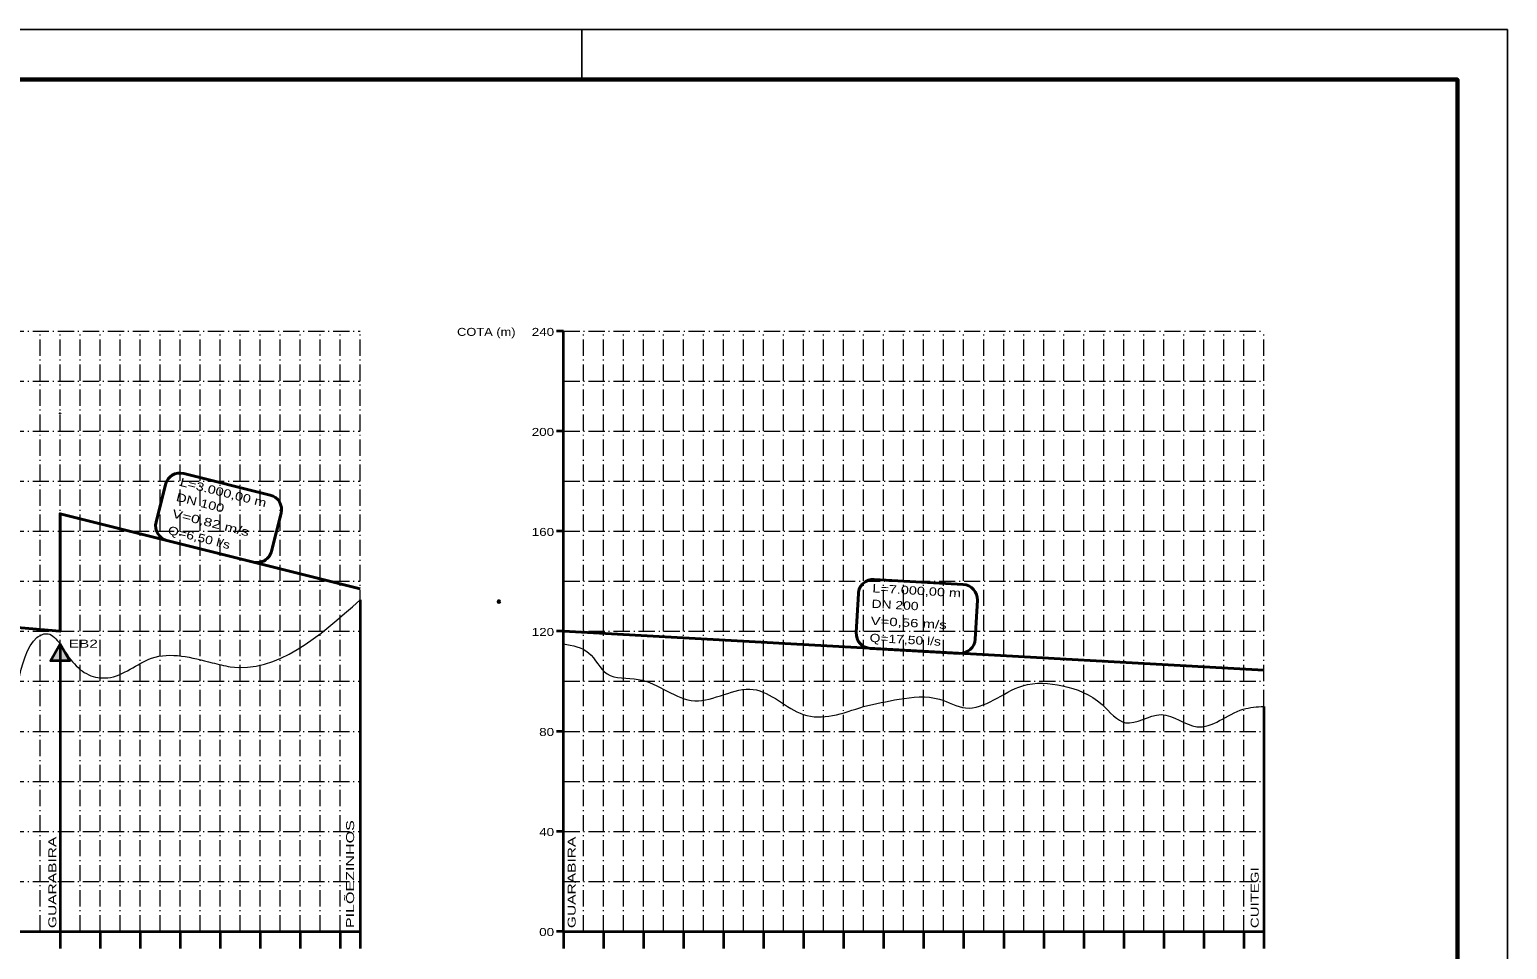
# Model space of a CAD drawing. Extents: x 0 to 1772, y 0 to 1188.
# Drawn here: x 1181 to 1772, y 820 to 1188 of the extents above; entities that cross this region are included whole.
import ezdxf
from ezdxf.enums import TextEntityAlignment as Align

# ---------------------------------------------------------------- set-up
doc = ezdxf.new("R2010")
doc.units = 0
doc.header["$LTSCALE"] = 1.3
doc.header["$PDMODE"] = 32
doc.header["$PDSIZE"] = 0.65
doc.linetypes.add('DOT_DASHED', pattern=[7.7, 5, -1.2, 0.3, -1.2])
for name, color, linetype, lineweight in [('1', 7, 'DOT_DASHED', 13), ('24', 7, 'Continuous', 35), ('55', 7, 'Continuous', 13), ('62', 7, 'Continuous', 13), ('63', 7, 'Continuous', 25), ('9', 7, 'Continuous', 40)]:
    doc.layers.add(name, color=color, linetype=linetype, lineweight=lineweight)

msp = doc.modelspace()

# ---------------------------------------------------------------- hatches: boundary and pattern name
at = {"layer": '62'}
msp.add_hatch(color=256, dxfattribs=at).paths.add_polyline_path([(1193.175, 942.213), (1197.121, 935.475), (1189.312, 935.427)])

# ---------------------------------------------------------------- linework, layer by layer
at = {"layer": '1'}
for p, q in [((121.175, 1067.213), (1313.175, 1067.213)), ((1185.175, 827.213), (1185.175, 1067.213)), ((1193.175, 827.213), (1193.175, 1067.213)), ((1201.175, 827.213), (1201.175, 1067.213)), ((1209.175, 827.213), (1209.175, 1067.213)), ((1217.175, 827.213), (1217.175, 1067.213)), ((1225.175, 827.213), (1225.175, 1067.213)), ((1233.175, 827.213), (1233.175, 1067.213)), ((1241.175, 827.213), (1241.175, 1067.213)), ((1249.175, 827.213), (1249.175, 1067.213)), ((1257.175, 827.213), (1257.175, 1067.213)), ((1265.175, 827.213), (1265.175, 1067.213)), ((1273.175, 827.213), (1273.175, 1067.213)), ((1281.175, 827.213), (1281.175, 1067.213)), ((1289.175, 827.213), (1289.175, 1067.213)), ((1297.175, 827.213), (1297.175, 1067.213)), ((1305.175, 827.213), (1305.175, 1067.213)), ((1313.175, 827.213), (1313.175, 1067.213)), ((1394.428, 1067.213), (1674.428, 1067.213)), ((1402.428, 827.213), (1402.428, 1067.213)), ((1410.428, 827.213), (1410.428, 1067.213)), ((1418.428, 827.213), (1418.428, 1067.213)), ((1426.428, 827.213), (1426.428, 1067.213)), ((1434.428, 827.213), (1434.428, 1067.213)), ((1442.428, 827.213), (1442.428, 1067.213)), ((1450.428, 827.213), (1450.428, 1067.213)), ((1458.428, 827.213), (1458.428, 1067.213)), ((1466.428, 827.213), (1466.428, 1067.213)), ((1474.428, 827.213), (1474.428, 1067.213)), ((1482.428, 827.213), (1482.428, 1067.213)), ((1490.428, 827.213), (1490.428, 1067.213)), ((1498.428, 827.213), (1498.428, 1067.213)), ((1506.428, 827.213), (1506.428, 1067.213)), ((1514.428, 827.213), (1514.428, 1067.213)), ((1522.428, 827.213), (1522.428, 1067.213)), ((1530.428, 827.213), (1530.428, 1067.213)), ((1538.428, 827.213), (1538.428, 1067.213)), ((1546.428, 827.213), (1546.428, 1067.213)), ((1554.428, 827.213), (1554.428, 1067.213)), ((1562.428, 827.213), (1562.428, 1067.213)), ((1570.428, 827.213), (1570.428, 1067.213)), ((1578.428, 827.213), (1578.428, 1067.213)), ((1586.428, 827.213), (1586.428, 1067.213)), ((1594.428, 827.213), (1594.428, 1067.213)), ((1602.428, 827.213), (1602.428, 1067.213)), ((1610.428, 827.213), (1610.428, 1067.213)), ((1618.428, 827.213), (1618.428, 1067.213)), ((1626.428, 827.213), (1626.428, 1067.213)), ((1634.428, 827.213), (1634.428, 1067.213)), ((1642.428, 827.213), (1642.428, 1067.213)), ((1650.428, 827.213), (1650.428, 1067.213)), ((1658.428, 827.213), (1658.428, 1067.213)), ((1666.428, 827.213), (1666.428, 1067.213)), ((1674.428, 827.213), (1674.428, 1067.213)), ((121.175, 1047.213), (1313.175, 1047.213)), ((1394.428, 1047.213), (1674.428, 1047.213)), ((121.175, 1027.213), (1313.175, 1027.213)), ((1394.428, 1027.213), (1674.428, 1027.213)), ((121.175, 1007.213), (1313.175, 1007.213)), ((1394.428, 1007.213), (1674.428, 1007.213)), ((121.175, 987.213), (1313.175, 987.213)), ((1394.428, 987.213), (1674.428, 987.213)), ((121.175, 967.213), (1313.175, 967.213)), ((1394.428, 967.213), (1674.428, 967.213)), ((121.175, 947.213), (1313.175, 947.213)), ((1394.428, 947.213), (1674.428, 947.213)), ((121.175, 927.213), (1313.175, 927.213)), ((1394.428, 927.213), (1674.428, 927.213)), ((121.175, 907.213), (1313.175, 907.213)), ((1394.428, 907.213), (1674.428, 907.213)), ((121.175, 887.213), (1313.175, 887.213)), ((1394.428, 887.213), (1674.428, 887.213)), ((121.175, 867.213), (1313.175, 867.213)), ((1394.428, 867.213), (1674.428, 867.213)), ((121.175, 847.213), (1313.175, 847.213)), ((1394.428, 847.213), (1674.428, 847.213))]:
    msp.add_line(p, q, dxfattribs=at)
at = {"layer": '55', "lineweight": 35}
for p, q in [((1313.175, 959.769), (1313.175, 827.213)), ((1193.175, 942.213), (1193.175, 827.213)), ((1674.428, 917.213), (1674.428, 827.213))]:
    msp.add_line(p, q, dxfattribs=at)
at = {"layer": '55'}
for points in [[(1193.175, 942.213), (1204.631, 929.827), (1212.201, 928.617), (1229.763, 936.48), (1253.986, 934.665), (1261.22, 933.061), (1313.175, 959.769)], [(121.175, 872.213), (130.775, 867.213), (132.775, 862.213), (134.775, 867.213), (136.375, 877.213), (137.975, 867.213), (139.575, 877.213), (149.175, 900.213), (153.175, 887.213), (155.575, 872.213), (165.975, 905.213), (181.975, 897.213), (202.775, 856.213), (243.575, 896.213), (251.575, 887.213), (258.775, 897.213), (274.775, 901.213), (282.775, 905.213), (304.375, 905.213), (317.175, 897.213), (325.175, 877.213), (326.775, 882.213), (328.375, 877.213), (345.175, 862.213), (359.575, 887.213), (384.375, 909.213), (405.175, 907.213), (418.775, 910.213), (450.775, 914.213), (458.775, 908.213), (491.575, 937.213), (505.175, 922.213), (509.175, 920.213), (541.175, 932.213), (550.775, 927.213), (553.175, 924.213), (567.575, 939.213), (575.575, 941.213), (595.575, 927.213), (605.175, 937.213), (611.575, 927.213), (623.575, 917.213), (632.375, 930.213), (648.375, 912.213), (668.375, 877.213), (669.975, 872.213), (676.375, 892.213), (679.575, 887.213), (685.975, 881.213), (704.375, 869.213), (713.975, 871.213), (720.375, 869.213), (724.375, 877.213), (728.375, 873.213), (745.175, 877.213), (748.375, 879.213), (750.775, 877.213), (769.975, 893.213), (784.375, 872.213), (804.375, 897.213), (822.775, 905.213), (842.775, 881.213), (846.775, 887.213), (853.975, 880.213), (857.975, 882.213), (862.775, 887.213), (866.775, 872.213), (870.775, 885.213), (880.375, 882.213), (894.775, 907.213), (927.575, 924.213), (940.375, 910.213), (953.175, 920.213), (971.575, 914.213), (985.975, 922.213), (1018.775, 902.213), (1038.775, 922.213), (1086.775, 937.213), (1105.175, 920.213), (1113.175, 927.213), (1120.375, 921.213), (1141.175, 942.213), (1165.175, 923.213), (1169.975, 927.213), (1173.175, 920.213), (1183.928, 944.69), (1188.375, 946.213), (1193.175, 942.213)], [(1394.428, 942.213), (1404.454, 938.633), (1411.856, 930.204), (1424.292, 927.986), (1446.943, 919.409), (1470.334, 923.993), (1490.32, 913.937), (1514.428, 917.213)], [(1514.428, 917.213), (1528.577, 920.068), (1544.702, 920.068), (1555.184, 916.573), (1578.027, 925.446), (1593.884, 925.446), (1609.74, 917.917), (1619.147, 910.657), (1633.39, 913.884), (1647.634, 909.044), (1666.178, 916.035), (1674.428, 917.213)]]:
    msp.add_spline(points, degree=3, dxfattribs=at)
at = {"layer": '62', "lineweight": 35}
for p, q in [((1394.428, 1067.213), (1391.697, 1067.213)), ((1394.26, 1067.213), (1394.428, 1067.213)), ((1394.428, 827.213), (1394.428, 1067.213)), ((1394.26, 1057.213), (1394.428, 1057.213)), ((1394.26, 1047.213), (1394.428, 1047.213)), ((1394.26, 1037.213), (1394.428, 1037.213)), ((1394.428, 1027.213), (1391.697, 1027.213)), ((1394.26, 1027.213), (1394.428, 1027.213)), ((1394.26, 1017.213), (1394.428, 1017.213)), ((1394.26, 1007.213), (1394.428, 1007.213)), ((1394.26, 997.213), (1394.428, 997.213)), ((1394.428, 987.213), (1391.697, 987.213)), ((1394.26, 987.213), (1394.428, 987.213)), ((1394.26, 977.213), (1394.428, 977.213)), ((1394.26, 967.213), (1394.428, 967.213)), ((1394.26, 957.213), (1394.428, 957.213)), ((1394.428, 947.213), (1391.697, 947.213)), ((1394.26, 947.213), (1394.428, 947.213)), ((1394.26, 937.213), (1394.428, 937.213)), ((1394.26, 927.213), (1394.428, 927.213)), ((1394.26, 917.213), (1394.428, 917.213)), ((1394.428, 907.213), (1391.697, 907.213)), ((1394.26, 907.213), (1394.428, 907.213)), ((1394.26, 897.213), (1394.428, 897.213)), ((1394.26, 887.213), (1394.428, 887.213)), ((1394.26, 877.213), (1394.428, 877.213)), ((1394.428, 867.213), (1391.697, 867.213)), ((1394.26, 867.213), (1394.428, 867.213)), ((1394.26, 857.213), (1394.428, 857.213)), ((1394.26, 847.213), (1394.428, 847.213)), ((1394.26, 837.213), (1394.428, 837.213)), ((1193.175, 827.213), (1193.175, 820.386)), ((1193.175, 827.213), (1313.175, 827.213)), ((1209.175, 827.213), (1209.175, 820.386)), ((1225.175, 827.213), (1225.175, 820.386)), ((1241.175, 827.213), (1241.175, 820.386)), ((1257.175, 827.213), (1257.175, 820.386)), ((1273.175, 827.213), (1273.175, 820.386)), ((1289.175, 827.213), (1289.175, 820.386)), ((1305.175, 827.213), (1305.175, 820.386)), ((1313.175, 827.213), (1313.175, 820.386)), ((1394.428, 827.213), (1391.697, 827.213)), ((1394.428, 827.213), (1394.428, 820.386)), ((1394.428, 827.213), (1674.428, 827.213)), ((1410.428, 827.213), (1410.428, 820.386)), ((1426.428, 827.213), (1426.428, 820.386)), ((1442.428, 827.213), (1442.428, 820.386)), ((1458.428, 827.213), (1458.428, 820.386)), ((1474.428, 827.213), (1474.428, 820.386)), ((1490.428, 827.213), (1490.428, 820.386)), ((1506.428, 827.213), (1506.428, 820.386)), ((1522.428, 827.213), (1522.428, 820.386)), ((1538.428, 827.213), (1538.428, 820.386)), ((1554.428, 827.213), (1554.428, 820.386)), ((1570.428, 827.213), (1570.428, 820.386)), ((1586.428, 827.213), (1586.428, 820.386)), ((1602.428, 827.213), (1602.428, 820.386)), ((1618.428, 827.213), (1618.428, 820.386)), ((1634.428, 827.213), (1634.428, 820.386)), ((1650.428, 827.213), (1650.428, 820.386)), ((1666.428, 827.213), (1666.428, 820.386)), ((1674.428, 827.213), (1674.428, 820.386))]:
    msp.add_line(p, q, dxfattribs=at)
at = {"layer": '62'}
for p, q in [((1394.26, 1065.213), (1394.428, 1065.213)), ((1394.26, 1063.213), (1394.428, 1063.213)), ((1394.26, 1061.213), (1394.428, 1061.213)), ((1394.26, 1059.213), (1394.428, 1059.213)), ((1394.26, 1055.213), (1394.428, 1055.213)), ((1394.26, 1053.213), (1394.428, 1053.213)), ((1394.26, 1051.213), (1394.428, 1051.213)), ((1394.26, 1049.213), (1394.428, 1049.213)), ((1394.26, 1045.213), (1394.428, 1045.213)), ((1394.26, 1043.213), (1394.428, 1043.213)), ((1394.26, 1041.213), (1394.428, 1041.213)), ((1394.26, 1039.213), (1394.428, 1039.213)), ((1394.26, 1035.213), (1394.428, 1035.213)), ((1394.26, 1033.213), (1394.428, 1033.213)), ((1394.26, 1031.213), (1394.428, 1031.213)), ((1394.26, 1029.213), (1394.428, 1029.213)), ((1394.26, 1025.213), (1394.428, 1025.213)), ((1394.26, 1023.213), (1394.428, 1023.213)), ((1394.26, 1021.213), (1394.428, 1021.213)), ((1394.26, 1019.213), (1394.428, 1019.213)), ((1394.26, 1015.213), (1394.428, 1015.213)), ((1394.26, 1013.213), (1394.428, 1013.213)), ((1394.26, 1011.213), (1394.428, 1011.213)), ((1394.26, 1009.213), (1394.428, 1009.213)), ((1394.26, 1005.213), (1394.428, 1005.213)), ((1394.26, 1003.213), (1394.428, 1003.213)), ((1394.26, 1001.213), (1394.428, 1001.213)), ((1394.26, 999.213), (1394.428, 999.213)), ((1394.26, 995.213), (1394.428, 995.213)), ((1394.26, 993.213), (1394.428, 993.213)), ((1394.26, 991.213), (1394.428, 991.213)), ((1394.26, 989.213), (1394.428, 989.213)), ((1394.26, 985.213), (1394.428, 985.213)), ((1394.26, 983.213), (1394.428, 983.213)), ((1394.26, 981.213), (1394.428, 981.213)), ((1394.26, 979.213), (1394.428, 979.213)), ((1394.26, 975.213), (1394.428, 975.213)), ((1394.26, 973.213), (1394.428, 973.213)), ((1394.26, 971.213), (1394.428, 971.213)), ((1394.26, 969.213), (1394.428, 969.213)), ((1394.26, 965.213), (1394.428, 965.213)), ((1394.26, 963.213), (1394.428, 963.213)), ((1394.26, 961.213), (1394.428, 961.213)), ((1394.26, 959.213), (1394.428, 959.213)), ((1394.26, 955.213), (1394.428, 955.213)), ((1394.26, 953.213), (1394.428, 953.213)), ((1394.26, 951.213), (1394.428, 951.213)), ((1394.26, 949.213), (1394.428, 949.213)), ((1394.26, 945.213), (1394.428, 945.213)), ((1394.26, 943.213), (1394.428, 943.213)), ((1394.26, 941.213), (1394.428, 941.213)), ((1394.26, 939.213), (1394.428, 939.213)), ((1394.26, 935.213), (1394.428, 935.213)), ((1394.26, 933.213), (1394.428, 933.213)), ((1394.26, 931.213), (1394.428, 931.213)), ((1394.26, 929.213), (1394.428, 929.213)), ((1394.26, 925.213), (1394.428, 925.213)), ((1394.26, 923.213), (1394.428, 923.213)), ((1394.26, 921.213), (1394.428, 921.213)), ((1394.26, 919.213), (1394.428, 919.213)), ((1394.26, 915.213), (1394.428, 915.213)), ((1394.26, 913.213), (1394.428, 913.213)), ((1394.26, 911.213), (1394.428, 911.213)), ((1394.26, 909.213), (1394.428, 909.213)), ((1394.26, 905.213), (1394.428, 905.213)), ((1394.26, 903.213), (1394.428, 903.213)), ((1394.26, 901.213), (1394.428, 901.213)), ((1394.26, 899.213), (1394.428, 899.213)), ((1394.26, 895.213), (1394.428, 895.213)), ((1394.26, 893.213), (1394.428, 893.213)), ((1394.26, 891.213), (1394.428, 891.213)), ((1394.26, 889.213), (1394.428, 889.213)), ((1394.26, 885.213), (1394.428, 885.213)), ((1394.26, 883.213), (1394.428, 883.213)), ((1394.26, 881.213), (1394.428, 881.213)), ((1394.26, 879.213), (1394.428, 879.213)), ((1394.26, 875.213), (1394.428, 875.213)), ((1394.26, 873.213), (1394.428, 873.213)), ((1394.26, 871.213), (1394.428, 871.213)), ((1394.26, 869.213), (1394.428, 869.213)), ((1394.26, 865.213), (1394.428, 865.213)), ((1394.26, 863.213), (1394.428, 863.213)), ((1394.26, 861.213), (1394.428, 861.213)), ((1394.26, 859.213), (1394.428, 859.213)), ((1394.26, 855.213), (1394.428, 855.213)), ((1394.26, 853.213), (1394.428, 853.213)), ((1394.26, 851.213), (1394.428, 851.213)), ((1394.26, 849.213), (1394.428, 849.213)), ((1394.26, 845.213), (1394.428, 845.213)), ((1394.26, 843.213), (1394.428, 843.213)), ((1394.26, 841.213), (1394.428, 841.213)), ((1394.26, 839.213), (1394.428, 839.213)), ((1394.26, 835.213), (1394.428, 835.213)), ((1394.26, 833.213), (1394.428, 833.213)), ((1394.26, 831.213), (1394.428, 831.213)), ((1394.26, 829.213), (1394.428, 829.213))]:
    msp.add_line(p, q, dxfattribs=at)
at = {"layer": '62', "lineweight": 35}
msp.add_lwpolyline([(1193.175, 942.213), (1197.121, 935.475), (1189.312, 935.427)], close=True, dxfattribs=at)
msp.add_lwpolyline([(121.175, 827.213), (401.175, 827.213), (1193.175, 827.213)], dxfattribs=at)
at = {"layer": '63'}
for p, q in [((-0.167, 1187.873), (1771.833, 1187.873)), ((1401.833, 1167.873), (1401.833, 1187.873)), ((1771.833, -0.127), (1771.833, 1187.873)), ((1771.833, -0.127), (1771.833, 1187.873))]:
    msp.add_line(p, q, dxfattribs=at)
msp.add_lwpolyline([(-0.167, -0.127), (1771.833, -0.127), (1771.833, 1187.873)], dxfattribs=at)
at = {"layer": '63', "lineweight": 60}
msp.add_lwpolyline([(49.833, 1167.873), (1751.833, 1167.873), (1751.833, 19.873), (49.833, 19.873)], close=True, dxfattribs=at)
at = {"layer": '63'}
msp.add_point((1751.833, 1167.873), dxfattribs=at)
at = {"layer": '9'}
for p, q in [((1235.318, 1005.98), (1231.527, 990.836)), ((1242.595, 1010.343), (1277.163, 1001.69)), ((1281.526, 994.413), (1277.736, 979.27)), ((689.175, 990.643), (1193.131, 947.217)), ((1235.891, 983.559), (1270.458, 974.906)), ((1518.667, 967.949), (1554.246, 965.968)), ((1512.343, 962.292), (1511.475, 946.705)), ((1559.903, 959.643), (1559.035, 944.057)), ((1394.428, 947.213), (1674.428, 931.622)), ((1517.132, 940.381), (1552.711, 938.4))]:
    msp.add_line(p, q, dxfattribs=at)
msp.add_lwpolyline([(1193.175, 947.213), (1193.175, 994.252), (1313.175, 964.213)], dxfattribs=at)
for centre, radius, start, end in [((1193.215, 1034.252), 0.04, 75.94642, 180), ((1241.138, 1004.523), 6, 75.94643, 165.94643), ((1275.706, 995.87), 6, 345.94643, 75.94643), ((1237.348, 989.379), 6, 165.94643, 255.94643), ((1271.915, 980.726), 6, 255.94643, 345.94643), ((1518.333, 961.958), 6, 86.81296, 176.81296), ((1553.912, 959.977), 6, 356.81296, 86.81296), ((1193.135, 947.257), 0.04, 265.07495, 0), ((1517.465, 946.372), 6, 176.81296, 266.81296), ((1553.044, 944.391), 6, 266.81296, 356.81296)]:
    msp.add_arc(centre, radius, start, end, dxfattribs=at)
msp.add_point((1368.605, 959.088), dxfattribs=at)

# ---------------------------------------------------------------- texts
at = {"layer": '24'}
for s, width, p in [('COTA (m)', 1.2, (1375.278, 1065.357)), ('240', 1.25, (1390.674, 1065.357)), ('200', 1.25, (1390.674, 1025.357)), ('160', 1.25, (1390.674, 985.357)), ('120', 1.25, (1390.674, 945.357)), ('80', 1.25, (1390.674, 905.357)), ('40', 1.25, (1390.674, 865.357)), ('00', 1.25, (1390.674, 825.357))]:
    msp.add_text(s, height=3.2, dxfattribs=dict(at, width=width)).set_placement(p, align=Align.RIGHT)
at = {"layer": '24', "width": 1.45}
msp.add_text('EB2', height=3.2, dxfattribs=at).set_placement((1196.576, 940.656))
at = {"layer": '24'}
for s, width, p in [('PILÕEZINHOS', 1.5, (1310.734, 828.53)), ('GUARABIRA', 1.45, (1191.682, 828.53)), ('GUARABIRA', 1.45, (1399.295, 828.53)), ('CUITEGI', 1.4, (1672.395, 828.53))]:
    msp.add_text(s, height=3.2, rotation=90, dxfattribs=dict(at, width=width)).set_placement(p)
at = {"layer": '9'}
for s, rotation, width, p in [('L=3.000,00 m', 345.946, 1.3, (1240.838, 1005.445)), ('DN 100', 345.946, 1.3, (1239.337, 999.45)), ('V=0,82 m/s', 345.946, 1.4, (1237.681, 992.83)), ('Q=6,50 l/s', 345.946, 1.25, (1236.024, 986.211)), ('L=7.000,00 m', 356.813, 1.3, (1517.865, 962.807)), ('DN 200', 356.813, 1.25, (1517.521, 956.636)), ('V=0,56 m/s', 356.813, 1.35, (1517.142, 949.823)), ('Q=17,50 l/s', 356.813, 1.25, (1516.762, 943.01))]:
    msp.add_text(s, height=3.319, rotation=rotation, dxfattribs=dict(at, width=width)).set_placement(p)

doc.saveas('drawing.dxf')
